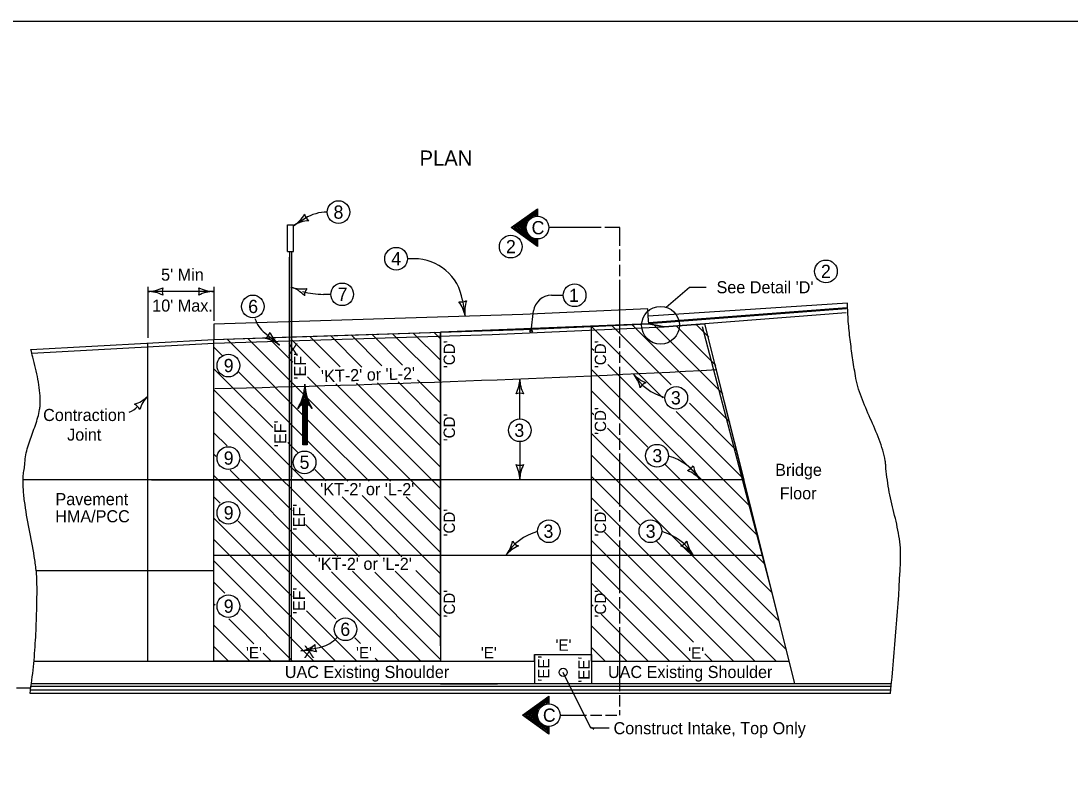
# Model space of a CAD drawing. Extents: x 10133 to 81668, y 7924 to 11018.
# Drawn here: x 10832 to 12222, y 8934 to 9944 of the extents above; entities that cross this region are included whole.
import ezdxf

# ---------------------------------------------------------------- set-up
doc = ezdxf.new("R2010")
doc.units = 0
for name, color, linetype in [('BridgeExistingStructure', 7, 'Continuous'), ('Cell', 7, 'Continuous'), ('Level 7', 7, 'Continuous'), ('RasterAttachment', 7, 'Continuous'), ('SheetBorder', 7, 'Continuous')]:
    doc.layers.add(name, color=color, linetype=linetype)

msp = doc.modelspace()

# ---------------------------------------------------------------- linework, layer by layer
at = {"layer": 'BridgeExistingStructure'}
msp.add_lwpolyline([(11387.6, 9532.2), (11387.6, 9096.8), (11512.2, 9096.8), (11512.2, 9105.5), (11587.6, 9105.5), (11587.6, 9096.8), (11849.2, 9096.8), (11737.5, 9543), (11683.5, 9539.4), (11663.2, 9543.1)], close=True, dxfattribs=at)
msp.add_lwpolyline([(11856.6, 9066.8), (11737.5, 9543), (11683.5, 9539.4), (11663.2, 9543.1), (11587.4, 9539.5), (11471.5, 9534.5)], dxfattribs=at)
at = {"layer": 'Cell'}
for p, q in [((11187.6, 9096.8), (11187.6, 9631.3)), ((11663.2, 9543.1), (11662.5, 9553.1)), ((11587.3, 9539.5), (11681.7, 9445.1)), ((11587.6, 9096.8), (11587.6, 9539.5)), ((11614.3, 9540.8), (11692.9, 9462.2)), ((11641.3, 9542), (11770.5, 9412.9)), ((11663.2, 9543.1), (11683.5, 9539.4)), ((11669.7, 9541.9), (11761.1, 9450.5)), ((11683.5, 9539.4), (11737.5, 9543)), ((11699.4, 9540.5), (11752.1, 9487.9)), ((11726, 9542.3), (11742.7, 9525.5)), ((11789.5, 9336.8), (11737.5, 9543)), ((10845.5, 9509.3), (11087.6, 9522.5)), ((11087.6, 9096.8), (11087.6, 9522.5)), ((11105.1, 9522.9), (11230.7, 9397.3)), ((11132.7, 9523.6), (11256.7, 9399.6)), ((11160.3, 9524.3), (11192, 9492.6)), ((11190.6, 9522.3), (11228, 9484.9)), ((11214.5, 9526.6), (11254.7, 9486.4)), ((11241.9, 9527.5), (11283.5, 9485.9)), ((11269.3, 9528.4), (11310, 9487.7)), ((11296.7, 9529.3), (11337.5, 9488.6)), ((11324.1, 9530.1), (11387.6, 9466.7)), ((11351.5, 9531), (11387.6, 9495)), ((11378.9, 9531.9), (11387.6, 9523.3)), ((11387.6, 9116.7), (11387.6, 9532.2)), ((10846.6, 9504.4), (11087.6, 9517.5)), ((11000.1, 9096.8), (11000.1, 9517.7)), ((11087.6, 9512.1), (11099, 9500.7)), ((11587.6, 9510.9), (11589.3, 9509.2)), ((11587.6, 9510.9), (11590.3, 9508.2)), ((11087.6, 9483.8), (11113.4, 9458.1)), ((11119.6, 9480.1), (11265.1, 9334.7)), ((11587.6, 9482.6), (11808, 9262.3)), ((11609, 9489.5), (11798.6, 9299.9)), ((11211.7, 9472.9), (11283.3, 9401.2)), ((11249.2, 9463.7), (11387.6, 9325.3)), ((11276.5, 9464.7), (11387.6, 9353.5)), ((11304.2, 9465.2), (11387.6, 9381.8)), ((11331.4, 9466.4), (11387.6, 9410.1)), ((11357, 9469), (11387.6, 9438.4)), ((11087.6, 9455.6), (11164.7, 9378.4)), ((11113.4, 9458.1), (11165.5, 9405.9)), ((11587.6, 9454.3), (11662, 9379.9)), ((11717, 9438.1), (11779.8, 9375.2)), ((11087.6, 9427.3), (11279.8, 9235.1)), ((11587.6, 9426), (11590.3, 9423.3)), ((11699.5, 9427.3), (11789.2, 9337.6)), ((11087.6, 9399), (11105.1, 9381.5)), ((11230.7, 9397.3), (11293.2, 9334.8)), ((11256.7, 9399.6), (11321.3, 9335)), ((11283.3, 9401.2), (11387.6, 9297)), ((11587.6, 9397.8), (11591.8, 9393.5)), ((11608.5, 9405.1), (11826.7, 9186.9)), ((11185.6, 9385.9), (11198.6, 9372.9)), ((11591.8, 9393.5), (11836.1, 9149.3)), ((11087.6, 9370.7), (11090.9, 9367.4)), ((11164.7, 9378.4), (11307.6, 9235.6)), ((11587.6, 9369.5), (11845.5, 9111.6)), ((11123.2, 9363.4), (11191.2, 9295.4)), ((11685.1, 9356.9), (11817.3, 9224.6)), ((11087.6, 9342.4), (11333.2, 9096.8)), ((11109, 9349.3), (11223.6, 9234.7)), ((11221.3, 9350.2), (11236.3, 9335.2)), ((11587.6, 9341.2), (11651.6, 9277.2)), ((11789.5, 9336.8), (10835.2, 9336.8)), ((11005.3, 9336.8), (11387.6, 9336.8)), ((11087.6, 9314.1), (11095.9, 9305.8)), ((11257.4, 9314.1), (11336.5, 9234.9)), ((11284, 9315.7), (11387.6, 9212.1)), ((11313.6, 9314.4), (11387.6, 9240.4)), ((11342.1, 9314.2), (11387.6, 9268.7)), ((11587.6, 9312.9), (11803.7, 9096.8)), ((11087.6, 9285.9), (11191.4, 9182)), ((11119.8, 9282), (11249.1, 9152.6)), ((11209.1, 9277.5), (11251.6, 9235)), ((11087.6, 9257.6), (11248.4, 9096.8)), ((11587.6, 9256.3), (11722.2, 9121.8)), ((11604.8, 9267.5), (11775.4, 9096.8)), ((11673.4, 9255.4), (11832, 9096.8)), ((11087.6, 9236.8), (11814.3, 9236.8)), ((11087.6, 9229.3), (11220.1, 9096.8)), ((11587.6, 9228.1), (11718.9, 9096.8)), ((11856.6, 9066.8), (11814.3, 9236.8)), ((10852.6, 9216.8), (11087.6, 9216.8)), ((11243.5, 9214.8), (11361.5, 9096.8)), ((11270.9, 9215.7), (11387.6, 9099)), ((11300.6, 9214.3), (11387.6, 9127.3)), ((11327.4, 9215.7), (11387.6, 9155.6)), ((11354.8, 9216.7), (11387.6, 9183.8)), ((11087.6, 9201), (11102.1, 9186.5)), ((11587.6, 9199.8), (11690.6, 9096.8)), ((11087.6, 9172.7), (11089.2, 9171.1)), ((11587.6, 9171.5), (11589.6, 9169.5)), ((11122.9, 9165.7), (11191.8, 9096.8)), ((11210.3, 9163.1), (11248.8, 9124.7)), ((11600.4, 9158.7), (11662.3, 9096.8)), ((11087.6, 9144.4), (11135.3, 9096.8)), ((11107.6, 9152.7), (11140.6, 9119.7)), ((11587.6, 9143.2), (11634, 9096.8)), ((11087.6, 9116.1), (11107, 9096.8)), ((11248.8, 9124.7), (11276.7, 9096.8)), ((11274.3, 9127.4), (11281.7, 9120.1)), ((11153, 9107.3), (11163.5, 9096.8)), ((11512.2, 9105.5), (11587.6, 9105.5)), ((11512.2, 9105.5), (11512.2, 9066.8)), ((11587.6, 9114.9), (11605.7, 9096.8)), ((11587.6, 9105.5), (11587.6, 9066.8)), ((11737.4, 9106.5), (11747.2, 9096.8)), ((10849.6, 9096.8), (11387.6, 9096.8)), ((11301, 9100.7), (11305, 9096.8)), ((11387.6, 9096.8), (11512.2, 9096.8)), ((11587.6, 9096.8), (11849.2, 9096.8)), ((11587.6, 9009.4), (11590.6, 9006.4))]:
    msp.add_line(p, q, dxfattribs=at)
for points in [[(11087.6, 9522.5), (11497.5, 9535.7), (11587.6, 9539.5), (11663.2, 9543.1)], [(11087.6, 9517.5), (11456.1, 9529), (11683.5, 9539.4)]]:
    msp.add_lwpolyline(points, dxfattribs=at)
msp.add_arc((10559.1, 32369.7), 22918.3, 271.32517, 272.98646, dxfattribs=at)
at = {"layer": 'Level 7'}
msp.add_line((11387.6, 9066.8), (11463.1, 9066.8), dxfattribs=at)
at = {"layer": 'RasterAttachment'}
for p, q in [((11185, 9674.1), (11193, 9674.1)), ((11185, 9638.9), (11185, 9674.1)), ((11193, 9638.9), (11193, 9674.1)), ((11208.4, 9682.7), (11193.5, 9673.3)), ((11624.8, 9670.5), (11605.2, 9670.5)), ((11624.8, 9655), (11624.8, 9670.5)), ((11624.8, 9646.4), (11624.8, 9670.5)), ((11185, 9638.9), (11193, 9638.9)), ((11187.6, 9638.9), (11187.6, 9340.8)), ((11190.6, 9638.9), (11190.6, 9340.8)), ((11352.5, 9629.4), (11343.8, 9629.4)), ((11000.1, 9592.2), (11000.1, 9524.4)), ((11087.6, 9592.2), (11087.6, 9547.2)), ((11686.1, 9565.1), (11716.9, 9591.8)), ((11716.9, 9591.8), (11739.2, 9591.8)), ((11087.6, 9586), (11000.1, 9586)), ((11242.4, 9582.2), (11232.8, 9582.2)), ((11416.7, 9574.6), (11420.1, 9553.3)), ((11534.3, 9580.9), (11550.1, 9580.9)), ((11662.5, 9553.1), (11661.9, 9563)), ((11926.1, 9570.6), (11662.5, 9553.1)), ((11925.2, 9564.5), (11663.1, 9544.5)), ((11925, 9563), (11663.2, 9543)), ((11507.4, 9533.7), (11510.7, 9560.2)), ((11924.4, 9557.6), (11737.5, 9543)), ((11087.6, 9542.5), (11087.6, 9522.5)), ((11826.7, 9186.9), (11734.2, 9539.1)), ((11814.3, 9236.8), (11737.5, 9543)), ((11174.4, 9515.1), (11154.9, 9531)), ((11492.5, 9417.2), (11492.5, 9470.4)), ((11205.2, 9436.1), (11205.2, 9436.1)), ((11208.2, 9436.2), (11208.2, 9383.2)), ((11211.4, 9436.1), (11211.4, 9436.1)), ((11492.5, 9387.2), (11492.5, 9336.8)), ((11187.6, 9096.8), (11187.6, 9340.8)), ((11190.6, 9096.8), (11190.6, 9340.8)), ((11248, 9125.4), (11251.1, 9128.3)), ((11202.7, 9110.1), (11227.5, 9114.7)), ((10845.4, 9060.8), (10826.4, 9060.8)), ((11983.7, 9063.2), (10845.7, 9063.2)), ((11984.1, 9066.8), (10846.2, 9066.8)), ((11624.8, 9056.8), (11624.8, 9071.8)), ((11983.1, 9054), (10844.4, 9054)), ((11983.6, 9058.4), (10845.1, 9058.4)), ((11624.8, 9036.8), (11624.8, 9051.8)), ((11624.8, 9025.1), (11624.8, 9031.8))]:
    msp.add_line(p, q, dxfattribs=at)
for points in [[(11515.9, 9655.5), (11515.9, 9645.5), (11480.9, 9670.5), (11515.9, 9695.5), (11515.9, 9685.5)], [(11514.9, 9686.4), (11515, 9693.7), (11482.8, 9670.5), (11515.1, 9647.1), (11514.9, 9654.8), (11513.5, 9655.1), (11514, 9649.6), (11484.9, 9670.5), (11514, 9691.7), (11513.7, 9686.3), (11512.7, 9686.1), (11512.8, 9689.6), (11486.9, 9670.4), (11512.8, 9652.1), (11512.3, 9655.2), (11511.2, 9655.5), (11511.3, 9654.5), (11489.1, 9670.7), (11511.7, 9687.7), (11510.6, 9685.8), (11491, 9670.8), (11503, 9661.3), (11502.3, 9663.1), (11493.1, 9670.9), (11502, 9677.7), (11501.1, 9675.9), (11495, 9671.1), (11501.1, 9665.8), (11500.5, 9668.1), (11496.5, 9671.2), (11500.6, 9674.4), (11500.4, 9672.7), (11498, 9671.3), (11500.3, 9669.9), (11500.2, 9671.4), (11499.4, 9671.3)], [(11600.2, 9670.5), (11530.9, 9670.5)], [(11624.8, 9626.4), (11624.8, 9641.4)], [(11624.8, 9606.4), (11624.8, 9621.4)], [(11624.8, 9531.4), (11624.8, 9601.4)], [(11661.9, 9563), (11496.7, 9555.7), (11087.6, 9542.5)], [(11624.8, 9511.4), (11624.8, 9526.4)], [(11624.8, 9491.4), (11624.8, 9506.4)], [(11624.8, 9416.4), (11624.8, 9486.4)], [(11215.1, 9434.7), (11211.5, 9436.9), (11206.2, 9437.2), (11201.7, 9435.3), (11204.9, 9443.1), (11207.6, 9452.3), (11208.2, 9454.8), (11209.5, 9448.2), (11212.8, 9438.6), (11214.3, 9435.8), (11203.2, 9436.8), (11208, 9450.9), (11212.1, 9437.1), (11204.5, 9437.7), (11208, 9447.4), (11210.2, 9438.5), (11205.8, 9438.1), (11207.8, 9444.2), (11209.1, 9439.5), (11207, 9439.3), (11207.6, 9441.5)], [(11211.2, 9436.1), (11211.2, 9383.2), (11205.2, 9383.2), (11205.2, 9436.1), (11210.3, 9436), (11210.5, 9383.9), (11205.7, 9384), (11205.9, 9435), (11209.5, 9435.1), (11209.7, 9384.6), (11206.5, 9384.7), (11206.5, 9434.3), (11208.8, 9434.4), (11209, 9385.2), (11207.2, 9385.3), (11207.3, 9433.6)], [(11624.8, 9396.4), (11624.8, 9411.4)], [(11624.8, 9376.4), (11624.8, 9391.4)], [(11624.8, 9301.4), (11624.8, 9371.4)], [(11624.8, 9281.5), (11624.8, 9296.5)], [(11624.8, 9261.5), (11624.8, 9276.5)], [(11624.8, 9186.5), (11624.8, 9256.5)], [(11624.8, 9166.5), (11624.8, 9181.5)], [(11624.8, 9146.5), (11624.8, 9161.5)], [(11624.8, 9071.5), (11624.8, 9141.5)], [(11611, 9007.9), (11586.7, 9007.9), (11549.9, 9081.8)], [(11530.9, 9010.1), (11530.9, 9000.1), (11495.9, 9025.1), (11530.9, 9050.1), (11530.9, 9040.1)], [(11530, 9041.1), (11530, 9048.4), (11497.8, 9025.1), (11530.1, 9001.7), (11529.9, 9009.4), (11528.5, 9009.8), (11529.1, 9004.2), (11499.9, 9025.1), (11529.1, 9046.3), (11528.8, 9041), (11527.7, 9040.7), (11527.8, 9044.3), (11501.9, 9025), (11527.9, 9006.8), (11527.3, 9009.9), (11526.2, 9010.2), (11526.3, 9009.1), (11504.1, 9025.4), (11526.7, 9042.4), (11525.6, 9040.5), (11506.1, 9025.5), (11518, 9016), (11517.3, 9017.7), (11508.1, 9025.6), (11517, 9032.4), (11516.2, 9030.6), (11510, 9025.8), (11516.2, 9020.4), (11515.6, 9022.8), (11511.6, 9025.9), (11515.6, 9029), (11515.4, 9027.4), (11513.1, 9026), (11515.3, 9024.6), (11515.2, 9026), (11514.4, 9026)], [(11545.9, 9025.1), (11580.9, 9025.1)], [(11585.9, 9025.1), (11600.9, 9025.1)], [(11605.9, 9025.1), (11620.9, 9025.1)]]:
    msp.add_lwpolyline(points, dxfattribs=at)
msp.add_lwpolyline([(11087.6, 9096.8), (11087.6, 9522.5), (11190.7, 9525.9), (11387.6, 9532.2), (11387.6, 9096.8)], close=True, dxfattribs=at)
for centre, radius in [((11252.6, 9691.1), 15), ((11515.9, 9670.5), 15), ((11480.5, 9645.3), 15), ((11328.8, 9629.4), 15), ((11897.7, 9612.6), 15), ((11257.4, 9582.2), 15), ((11565.1, 9580.9), 15), ((11139.2, 9566.2), 15), ((11678.8, 9541.2), 25), ((11507.4, 9533.7), 1.78), ((11106.8, 9487.9), 15), ((11699.6, 9445.2), 15), ((11492.5, 9402.2), 15), ((11106.8, 9365.5), 15), ((11674.1, 9368.6), 15), ((11207.7, 9359.8), 15), ((11106.8, 9293), 15), ((11531, 9268.6), 15), ((11665.3, 9268.6), 15), ((11106.8, 9169.4), 15), ((11261.8, 9138.8), 15), ((11549.9, 9081.8), 5.42), ((11530.9, 9025.1), 15)]:
    msp.add_circle(centre, radius, dxfattribs=at)
for centre, radius, start, end in [((11171, 9709.4), 42.5, 302.0836, 330.1561), ((11223.7, 9692.3), 16.4, 194.3502, 229.8169), ((11237.6, 9636.1), 55, 90, 122.0832), ((11216.1, 9637.3), 42.5, 94.0111, 122.0836), ((11352.5, 9564.4), 65, 9.0332, 90), ((11000.1, 9628.5), 42.5, 270, 298.0725), ((11035.7, 9586), 16.4, 162.2666, 197.7334), ((11052, 9586), 16.4, 342.2666, 17.7334), ((11087.6, 9628.5), 42.5, 241.9275, 270), ((11176.2, 9551.6), 42.5, 42.7463, 70.8188), ((11204.2, 9631.9), 42.5, 250.8188, 278.8913), ((11223.8, 9580), 16.4, 143.0855, 178.5522), ((11000.1, 9543.5), 42.5, 61.9275, 90), ((11087.6, 9543.5), 42.5, 90, 118.0725), ((11232.8, 9682.2), 100, 253.9209, 270.0004), ((11534.3, 9557.2), 23.7, 90, 172.7713), ((11414.5, 9588.5), 16.4, 261.2988, 296.7655), ((11378.1, 9546.6), 42.5, 9.0322, 37.1047), ((11462.1, 9559.9), 42.5, 160.9597, 189.0322), ((11180.3, 9562), 40, 196.9407, 230.6061), ((11146.9, 9537.7), 16.4, 302.8729, 338.3396), ((11147.4, 9482.2), 42.5, 50.6062, 78.6787), ((11201.4, 9547.9), 42.5, 202.5337, 230.6062), ((11702.5, 9513.6), 70.1, 211.4011, 255.2124), ((11610.4, 9449.4), 42.5, 12.5555, 40.628), ((11674.9, 9504.8), 42.5, 220.628, 248.7005), ((11143.7, 9465.1), 64.5, 328.2857, 358.3158), ((11272.6, 9465.1), 64.5, 181.6842, 211.7143), ((11450, 9470.4), 42.5, 331.9275, 360), ((11535, 9470.4), 42.5, 180, 208.0725), ((11665.8, 9450.1), 16.4, 112.8947, 148.3614), ((11492.5, 9434.8), 16.4, 72.2666, 107.7334), ((10969.9, 9477.3), 42.5, 287.1795, 315.252), ((10975, 9422.1), 16.4, 27.5186, 62.9854), ((11030.3, 9417.5), 42.5, 135.252, 163.3245), ((11208.2, 9425.2), 11.3, 31.7147, 148.2853), ((10960.1, 9460.3), 37.5, 294.4548, 315.2539), ((11671.2, 9300.3), 70.1, 31.4011, 75.2124), ((11492.5, 9372.4), 16.4, 252.2666, 287.7333), ((11450, 9336.8), 42.5, 360, 28.0725), ((11535, 9336.8), 42.5, 151.9275, 180), ((11708.2, 9364.2), 16.4, 292.0277, 327.4944), ((11763.7, 9364), 42.5, 191.6886, 219.7611), ((11698.4, 9309.6), 42.5, 39.7611, 67.8336), ((11533.9, 9200.3), 70.1, 104.7876, 148.5989), ((11441.1, 9263.6), 42.5, 320.9096, 348.9821), ((11496.6, 9264.4), 16.4, 213.1763, 248.643), ((11662.4, 9200.3), 70.1, 31.4011, 75.2124), ((11699.8, 9264.4), 16.4, 291.357, 326.8237), ((11755.2, 9263.6), 42.5, 191.0179, 219.0904), ((11507.1, 9210), 42.5, 112.8371, 140.9096), ((11689.2, 9210), 42.5, 39.0904, 67.1629), ((11194.9, 9151.9), 42.5, 280.5658, 308.6383), ((11237.7, 9116.6), 16.4, 172.8325, 208.2992), ((11220.1, 9154.1), 40, 280.5659, 314.2313), ((11210.5, 9068.3), 42.5, 72.4933, 100.5658)]:
    msp.add_arc(centre, radius, start, end, dxfattribs=at)
for points in [[(11977.1, 9351.8), (11976.8, 9356.6), (11976.2, 9361.8), (11972.9, 9376.1), (11968.1, 9390.2), (11956.4, 9418), (11944.6, 9445.9), (11939.9, 9460.1), (11936.7, 9474.5), (11934.8, 9486.4), (11933, 9498.3), (11929.7, 9522.2), (11927.3, 9546.3), (11926.1, 9570.6)], [(10837.4, 9356.4), (10838.3, 9367.1), (10840.6, 9377.6), (10847.7, 9398.5), (10854.7, 9419.4), (10857, 9429.9), (10857.7, 9435.1), (10857.9, 9440.4), (10857.1, 9455.1), (10854.8, 9469.7), (10847.9, 9499.1), (10845.5, 9509.3)], [(10844.4, 9054), (10848.9, 9089.1), (10851.6, 9124.2), (10853.1, 9159.3), (10853.5, 9176.8), (10853.6, 9194.2), (10852.9, 9212.5), (10850.7, 9230.8), (10844.1, 9267.3), (10837.7, 9303.8), (10835.7, 9322), (10835.3, 9331.2), (10835.3, 9340.3), (10835.6, 9344.3), (10836.3, 9348.3), (10837, 9352.4), (10837.4, 9356.4)], [(11983.1, 9054), (11996.2, 9227.3), (11996.4, 9242.9), (11994.9, 9258.4), (11988.6, 9289.5), (11981.4, 9320.5), (11977.1, 9351.8)]]:
    msp.add_spline(points, degree=3, dxfattribs=at)
at = {"layer": 'SheetBorder'}
msp.add_line((11087.6, 9096.8), (11359.4, 9096.8), dxfattribs=at)
msp.add_lwpolyline([(10132.5, 9944), (13267.5, 9944), (13267.5, 7924), (10132.5, 7924)], close=True, dxfattribs=at)

# ---------------------------------------------------------------- texts
at = {"layer": 'BridgeExistingStructure'}
for s, height, p in [('PLAN ', 20, (11359.8, 9752.6)), ('8', 17.5, (11246, 9682.3)), ('C', 17.5, (11508.1, 9661.7)), ('2', 17.5, (11474.2, 9636.6)), ('4', 17.5, (11322.4, 9620.6)), ("5' Min", 16, (11017.8, 9600.3)), ('2', 17.5, (11891.1, 9603.9)), ('7', 17.5, (11251.4, 9573.5)), ('1', 17.5, (11557.7, 9572.2)), ("See Detail 'D'", 16, (11752.9, 9583.6)), ("10' Max.", 16, (11006.1, 9559.3)), ('6', 17.5, (11133.1, 9557.4)), ('X', 16, (11185.2, 9501.2)), ('9', 17.5, (11100.7, 9479.2)), ('3', 17.5, (11692.5, 9436.5)), ('Contraction', 16, (10861.7, 9414.5)), ('3', 17.5, (11485.4, 9393.5)), ('Joint', 16, (10893.5, 9388.5)), ('9', 17.5, (11100.7, 9356.7)), ('5', 17.5, (11201.1, 9351.1)), ('3', 17.5, (11668, 9359.9)), ('Bridge', 16, (11830.5, 9341.9)), ("'KT-2' or 'L-2'", 16, (11228.4, 9316.3)), ('Floor', 16, (11836.5, 9310.9)), ('Pavement', 16, (10878, 9303.1)), ('HMA/PCC', 16, (10877.7, 9280.4)), ('9', 17.5, (11100.7, 9284.3)), ('3', 17.5, (11523.9, 9259.9)), ('3', 17.5, (11659.2, 9259.9)), ("'KT-2' or 'L-2'", 16, (11225.1, 9217.5)), ('9', 17.5, (11100.7, 9160.7)), ('6', 17.5, (11255, 9130.1)), ('X', 16, (11206.6, 9101)), ("'E'", 15, (11539.8, 9110.4)), ("'E'", 15, (11130.2, 9100.4)), ("'E'", 15, (11275.8, 9100.4)), ("'E'", 15, (11441, 9100.4)), ("'E'", 15, (11715.4, 9100)), ('UAC Existing Shoulder', 16, (11181.5, 9074.3)), ('UAC Existing Shoulder', 16, (11609.2, 9074.3)), ('C', 17.5, (11523.1, 9016.4)), ('Construct Intake, Top Only', 16, (11616.6, 8999.9))]:
    msp.add_text(s, height=height, dxfattribs=at).set_placement(p)
for s, height, rotation, p in [("'CD'", 15, 90, (11406.7, 9484.5)), ("'CD'", 15, 90, (11606.7, 9484.5)), ("'EF'", 16, 90, (11209.7, 9469.3)), ("'KT-2' or 'L-2'", 16, 1.8809, (11229.8, 9465.8)), ("'CD'", 15, 90, (11406.7, 9387.7)), ("'CD'", 15, 90, (11606.7, 9396.2)), ("'EF'", 16, 90, (11183.6, 9379.9)), ("'EF'", 16, 90, (11208.4, 9269.5)), ("'CD'", 15, 90, (11406.7, 9261.7)), ("'CD'", 15, 90, (11606.7, 9261.7)), ("'EF'", 16, 90, (11208.4, 9158.8)), ("'CD'", 15, 90, (11406.7, 9154.4)), ("'CD'", 15, 90, (11606.7, 9154.4)), ("'EE'", 15, 90, (11531.6, 9069.6)), ("'EE'", 15, 90, (11584.9, 9068.1))]:
    msp.add_text(s, height=height, rotation=rotation, dxfattribs=at).set_placement(p)

doc.saveas('drawing.dxf')
